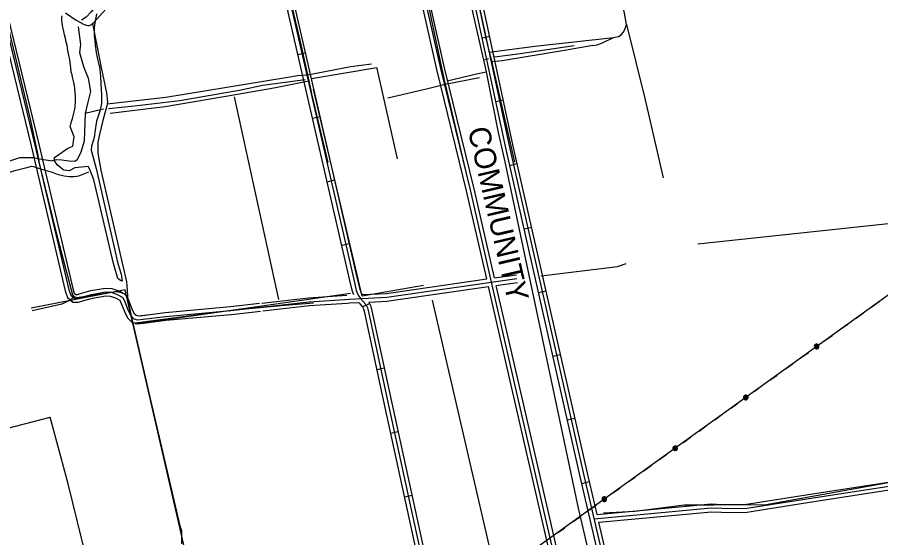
# Model space of a CAD drawing. Extents: x 3424494 to 3462436, y 522220 to 547718.
# Drawn here: x 3456047 to 3459355, y 534289 to 536285 of the extents above; entities that cross this region are included whole.
import ezdxf

# ---------------------------------------------------------------- set-up
doc = ezdxf.new("R2010")
doc.units = 0
for name, color, linetype in [('V-DTCH-CNTR', 7, 'Continuous'), ('V-RIVR-IDEN', 7, 'Continuous'), ('V-ROAD-CNTR', 7, 'Continuous'), ('V-SITE-VEGE', 7, 'Continuous'), ('V-TOPO-SHOR', 7, 'Continuous'), ('V-UTIL-LINE', 7, 'Continuous')]:
    doc.layers.add(name, color=color, linetype=linetype)

msp = doc.modelspace()

# ---------------------------------------------------------------- linework, layer by layer
at = {"layer": 'V-DTCH-CNTR'}
for points in [[(3456711.5, 540227.9), (3456791.8, 539883.8), (3456931.2, 539302.5), (3457055.3, 538754), (3457152.5, 538348.2), (3457303.4, 537680.5), (3457454.1, 537049.8), (3457610.6, 536382.1), (3457681.2, 536050.2), (3457686.5, 536027.5), (3457762.9, 535702)], [(3456761.3, 537785.8), (3456807.2, 537593.5), (3456918.5, 537101.2), (3456990.2, 536787.4), (3456997.1, 536757.5), (3457129.5, 536196.9)], [(3457694.3, 536907.7), (3457839.9, 536215.2), (3457855.4, 536151.1), (3457864.6, 536113), (3457869.4, 536093.2), (3457951.2, 535728.4)], [(3458335.6, 536207.6), (3458350.7, 536210.4), (3458360.2, 536217.3), (3458368.4, 536225.6), (3458373.8, 536238), (3458380.6, 536257.3), (3458373.5, 536299.8), (3458305.7, 536609.7), (3458305.7, 536613.8), (3458308.4, 536617.9), (3458437.3, 536642.1), (3458507.3, 536650.7), (3458588.2, 536662.2), (3458628, 536672), (3458759.6, 536703), (3458780.2, 536707.3), (3458905, 536723.1), (3459238.4, 536770.4), (3459485.3, 536802.1), (3459562.6, 536812.9)], [(3455947.2, 536511.2), (3455964.6, 536439.9), (3456097.1, 535894), (3456124.7, 535762.5), (3456131.3, 535725.6), (3456136.6, 535703.6), (3456196.8, 535458), (3456259.1, 535220.3), (3456264.8, 535212.2), (3456268.2, 535212.2), (3456275.1, 535209.8), (3456426.1, 535232.6), (3456439.9, 535230.2), (3456445.6, 535229), (3456454.8, 535225.4), (3456460.5, 535220.8), (3456462.8, 535218.5), (3456470.7, 535198.8), (3456490.4, 535112.3), (3456554.8, 534828.6), (3456670.1, 534334.8), (3456675.7, 534316.4), (3456676.7, 534295.7), (3456676.4, 534265.7)], [(3456231.6, 536301.3), (3456272.8, 536273.3), (3456303.7, 536256.9), (3456317.5, 536253.3), (3456320.9, 536253.3), (3456324.4, 536253.2), (3456331.3, 536256.6), (3456335.6, 536260.4), (3456341.8, 536265.7), (3456429, 536363.9)], [(3456335.6, 536260.4), (3456368.1, 536091.3), (3456389, 535994.5), (3456392.8, 535959.1), (3456391.4, 535952.6), (3456390, 535945.5), (3456374.5, 535888.5), (3456361.7, 535835.5), (3456356, 535805.6), (3456355.8, 535785.2), (3456355.7, 535763.4), (3456367.3, 535698), (3456451.1, 535331.1), (3456465.5, 535269.7), (3456466.8, 535254.8), (3456470.7, 535198.8)], [(3458380.6, 536257.3), (3458452.4, 535968), (3458521.4, 535669.1)], [(3457855.4, 536151.1), (3458029.6, 536174.2), (3458331, 536207.1), (3458335.6, 536207.6)], [(3458251.5, 536176.1), (3458267.9, 536178.9), (3458288.5, 536185.9), (3458331, 536207.1)], [(3457129.5, 536196.9), (3457158.6, 536064.4), (3457163.7, 536041.2), (3457174.6, 535991.3), (3457236.6, 535728)], [(3458251.5, 536176.1), (3458143.7, 536157.4), (3457905.1, 536117.6), (3457864.6, 536113)], [(3457083.8, 536055.2), (3457120.8, 536060.9), (3457158.6, 536064.4), (3457324.5, 536095.6), (3457404.1, 536105.7)], [(3456391.4, 535952.6), (3456616.2, 535977.8), (3457083.8, 536055.2)], [(3456402.9, 535917), (3456614.2, 535943), (3456891.3, 535990), (3457029.8, 536014.2), (3457163.7, 536041.2)], [(3457466.1, 535976.2), (3457619.6, 536011.4), (3457686.5, 536027.5), (3457818.2, 536053)], [(3455890.7, 535533.4), (3456008.4, 535559.9), (3456005.1, 535578.4), (3455989.9, 535677.5), (3455991, 535679.8), (3455992.2, 535683.2), (3456043, 535697.7), (3456089.2, 535710), (3456101.9, 535713.3), (3456109.9, 535712.1), (3456136.6, 535703.6), (3456180.3, 535690.6), (3456199.8, 535683.5), (3456227.3, 535676.3), (3456245.7, 535673.8), (3456264.1, 535673.7), (3456275.7, 535675.9), (3456282.6, 535677), (3456321.9, 535691.6)], [(3456268.2, 535212.2), (3456245.1, 535197.4), (3456235.8, 535192.9), (3456217.3, 535185), (3456104.3, 535158.4)], [(3456490.4, 535112.3), (3456866.5, 535162), (3457058.5, 535179.3), (3457182.5, 535189.1)], [(3455732.6, 534638.6), (3455788.5, 534651.7), (3455905.8, 534682), (3456173.2, 534751.7)], [(3456368.4, 533980.3), (3456242.4, 534495.9), (3456173.2, 534751.7)]]:
    msp.add_lwpolyline(points, dxfattribs=at)
at = {"layer": 'V-ROAD-CNTR'}
for p, q in [((3457827.5, 536205.6), (3457856.8, 536211.9)), ((3457122.5, 536141.4), (3457151.7, 536148.1)), ((3457879.9, 535961.1), (3457909.2, 535967.4)), ((3457178.5, 535897.7), (3457207.7, 535904.5)), ((3457933.1, 535716.7), (3457962.4, 535723.3)), ((3457234.5, 535654.1), (3457263.7, 535660.8)), ((3457988.3, 535472.9), (3458017.6, 535479.5)), ((3457290.5, 535410.4), (3457319.7, 535417.2)), ((3458043.5, 535229), (3458072.8, 535235.7)), ((3457369.8, 535174.3), (3457396.9, 535187)), ((3458098.8, 534985.2), (3458128, 534991.8)), ((3457424.5, 534934.1), (3457453.8, 534940.4)), ((3458154, 534741.4), (3458183.2, 534748)), ((3457477.2, 534689.7), (3457506.5, 534696.1)), ((3458209.4, 534497.5), (3458238.6, 534504.3)), ((3457530.3, 534445.4), (3457559.6, 534451.8))]:
    msp.add_line(p, q, dxfattribs=at)
for points in [[(3455205.2, 539547.1), (3455574.6, 538012.3), (3455861.5, 536771.8), (3456100.5, 535791.1), (3456230.8, 535235.5), (3456240.2, 535209.6), (3456260.4, 535192.5), (3456269.6, 535192.1)], [(3455234.4, 539554.1), (3455603.8, 538019.2), (3455890.7, 536778.8), (3456129.7, 535798.1), (3456259.6, 535244.1), (3456265.7, 535227.3), (3456272, 535222), (3456277.7, 535221.8), (3456293.7, 535227), (3456328.4, 535236.4), (3456384.6, 535246.5), (3456409.5, 535245), (3456436.1, 535235.8), (3456462.9, 535221.1), (3456472.7, 535199.3), (3456486, 535166.5), (3456494.2, 535149.6), (3456502, 535142), (3456509.2, 535139.7), (3456520.7, 535141)], [(3457845.7, 535281.1), (3457768.1, 535619.6), (3457654.7, 536084.1), (3457424.3, 537108.7), (3457105, 538484.3)], [(3457904.4, 532804), (3458333.9, 532953.1), (3458352.1, 532961.5), (3458363.3, 532968.4), (3458372.4, 532976.8), (3458379.6, 532986.3), (3458384.6, 532993.3), (3458381.1, 533017.4), (3458365.7, 533088.2), (3458203.9, 533788.7), (3458064.2, 534393.6), (3457920.5, 535022), (3457782.7, 535623.1), (3457669.3, 536087.5), (3457438.9, 537112), (3457119.7, 538487.7)], [(3457875.5, 535285.4), (3457797.3, 535626.5), (3457684, 536090.9), (3457453.6, 537115.4), (3457134.3, 538491.1)], [(3457336.2, 535220), (3457331.3, 535232.6), (3457321.5, 535275.4), (3457095.3, 536259.6), (3456835.7, 537394.7), (3456660.7, 538154)], [(3456675.3, 538157.4), (3456850.3, 537398), (3457109.9, 536262.9), (3457336.2, 535278.8), (3457345.7, 535237), (3457352.7, 535219), (3457361.5, 535206.2), (3457372.4, 535195.2), (3457382.3, 535183), (3457388.2, 535170.3), (3457392.6, 535154.9), (3457464.1, 534820.3), (3457607.2, 534162.5), (3457709.5, 533697.4), (3457808.4, 533253.8), (3458020.8, 532281.5), (3458061.7, 532076.5), (3458111.7, 531839.8), (3458138.7, 531712.3)], [(3457369.1, 535221.6), (3457366.1, 535226), (3457360.1, 535241.4), (3457350.8, 535282.1), (3457124.6, 536266.3), (3456864.9, 537401.4), (3456690, 538160.8)], [(3457542.8, 537607.4), (3457689.1, 536922.3), (3457932.7, 535786.6), (3458217.8, 534527.5), (3458420.3, 533657.6), (3458593.6, 532915.5), (3458790.6, 532085.6), (3458862.3, 531774.7)], [(3458405.7, 533654.2), (3458203.2, 534524.2), (3457918, 535783.4), (3457674.4, 536919.1)], [(3458268, 534378), (3458232.4, 534530.9), (3457947.3, 535789.8), (3457703.8, 536925.4)], [(3455876.1, 536775.3), (3456115.1, 535794.6), (3456245.2, 535239.8), (3456253, 535218.5), (3456266.2, 535207.2), (3456279.8, 535206.7), (3456298, 535212.7), (3456331.7, 535221.7), (3456385.5, 535231.4), (3456406.6, 535230.2), (3456430, 535222), (3456451.2, 535210.3), (3456458.9, 535193.4), (3456472.3, 535160.4), (3456481.8, 535140.8), (3456494, 535128.8), (3456507.7, 535124.4), (3456529, 535126.8), (3456615.2, 535137.8), (3456865, 535160.3), (3457164.7, 535194), (3457320, 535204.3), (3457462.8, 535210.9), (3457961.3, 535282.6)], [(3457369.1, 535221.6), (3457461.3, 535225.8), (3457845.7, 535281.1)], [(3457875.5, 535285.4), (3457959.2, 535297.4)], [(3457497.1, 535200.6), (3457852.5, 535251.8)], [(3457917.6, 532824.4), (3458328.3, 532967), (3458345, 532974.8), (3458354.2, 532980.4), (3458361.2, 532986.9), (3458367.5, 532995.2), (3458368.9, 532997.1), (3458366.3, 533014.7), (3458351.1, 533085), (3458189.3, 533785.3), (3458049.6, 534390.2), (3457905.9, 535018.7), (3457852.5, 535251.8)], [(3457882.2, 535256.1), (3457963.4, 535267.7)], [(3458395.7, 532983), (3458400.3, 532989.5), (3458395.9, 533020.1), (3458380.4, 533091.5), (3458218.5, 533792.1), (3458078.9, 534397), (3457935.2, 535025.4), (3457882.2, 535256.1)], [(3456269.6, 535192.1), (3456281.9, 535191.6), (3456302.3, 535198.3), (3456334.9, 535207.1), (3456386.4, 535216.3), (3456403.6, 535215.3), (3456423.9, 535208.3), (3456439.6, 535199.6), (3456445.1, 535187.5), (3456458.6, 535154.3), (3456469.4, 535131.9), (3456486.1, 535115.6), (3456494.6, 535112.8)], [(3456984.3, 535188.8), (3457163.3, 535208.9), (3457309.4, 535218.6)], [(3456515.2, 535140.3), (3456527.2, 535141.7), (3456613.5, 535152.7), (3456863.5, 535175.2), (3456864.2, 535175.3)], [(3456864.2, 535175.3), (3456975.3, 535187.8)], [(3456987.6, 535159), (3457166, 535179), (3457311.4, 535188.7)], [(3457311.4, 535188.7), (3457320.9, 535189.3), (3457355.5, 535190.9)], [(3458124, 531709.2), (3458097, 531836.6), (3458047.1, 532073.5), (3458006.1, 532278.4), (3457793.8, 533250.6), (3457694.9, 533694.1), (3457592.5, 534159.3), (3457449.5, 534817.2), (3457378.1, 535151.2), (3457374.1, 535165), (3457369.4, 535175), (3457361.2, 535185.2), (3457355.5, 535190.9)], [(3457393.7, 535192.7), (3457464.2, 535195.9), (3457497.1, 535200.6)], [(3457917.6, 532824.4), (3457823.1, 533257.1), (3457724.2, 533700.6), (3457621.8, 534165.7), (3457478.8, 534823.5), (3457407.2, 535158.5), (3457402.3, 535175.5), (3457395.1, 535191), (3457393.7, 535192.7)], [(3456518.7, 535110.5), (3456530.8, 535111.9), (3456616.8, 535122.8), (3456866.5, 535145.4), (3456867.5, 535145.5)], [(3456520.7, 535141), (3456527.2, 535141.7), (3456550.6, 535144.7)], [(3456867.5, 535145.5), (3456978.6, 535158)], [(3456494.6, 535112.8), (3456506.2, 535109.1), (3456518.7, 535110.5)], [(3458256.4, 534361.8), (3458705.7, 534403.4), (3458745.7, 534401.9), (3458833.5, 534401.1), (3459071.9, 534438.5), (3459377.4, 534485.7), (3459756.2, 534548.5), (3459927.3, 534575.6), (3460055.3, 534584)], [(3458268, 534378), (3458705.3, 534418.4), (3458746, 534416.9), (3458832.4, 534416.1), (3459069.6, 534453.3), (3459375.1, 534500.5), (3459753.8, 534563.4), (3459925.6, 534590.5), (3460036.9, 534597.8)], [(3458274.9, 534348.5), (3458706.1, 534388.4), (3458745.3, 534386.9), (3458834.6, 534386.1), (3459074.2, 534423.7), (3459379.8, 534470.9), (3459758.6, 534533.7), (3459928.9, 534560.6), (3460043.4, 534568.1)], [(3458512, 533330.6), (3458434.9, 533661), (3458274.9, 534348.5)]]:
    msp.add_lwpolyline(points, dxfattribs=at)
at = {"layer": 'V-SITE-VEGE'}
msp.add_lwpolyline([(3456350.9, 536297.3), (3456347.5, 536281.5), (3456346.6, 536276.7), (3456344.8, 536262.8), (3456342.1, 536244.9), (3456341.6, 536238.2), (3456341.8, 536226), (3456342.2, 536216.4), (3456343.2, 536201.5), (3456343.7, 536196.7), (3456345.3, 536177), (3456349.1, 536149.8), (3456354.8, 536123.6), (3456357.6, 536114), (3456359.8, 536104), (3456361.7, 536095.3), (3456363.6, 536081.7), (3456364.7, 536071.5), (3456366, 536055.6), (3456368.4, 536007.5), (3456369.6, 535986.8), (3456370.2, 535973.5), (3456369.5, 535954.4), (3456367.5, 535942.8), (3456363, 535924), (3456351, 535886), (3456347.7, 535869.7), (3456346.8, 535861.8), (3456345.4, 535852), (3456344.7, 535845.1), (3456343.1, 535832.5), (3456341.2, 535824), (3456337.4, 535810.9), (3456331.6, 535790.5), (3456330.6, 535775), (3456349.9, 535705.3), (3456432.4, 535341), (3456444.6, 535299.7), (3456449.4, 535272.9), (3456442.2, 535275.4), (3456432.4, 535282.7), (3456415.5, 535341), (3456340.2, 535661.6), (3456325.6, 535700.4), (3456318.4, 535712.6), (3456267.4, 535707.7), (3456245.5, 535695.6), (3456226.1, 535698), (3456201.8, 535717.4), (3456189.7, 535734.4), (3456189.7, 535746.6), (3456206.7, 535758.7), (3456240.7, 535783), (3456260.1, 535790.3), (3456264.9, 535826.7), (3456249.2, 535865.9), (3456252.5, 535876.5), (3456256, 535888.6), (3456258.2, 535896.5), (3456264.3, 535917.1), (3456267.5, 535932.4), (3456269.1, 535942.9), (3456270.2, 535960.2), (3456270.4, 535972), (3456270.2, 535982.9), (3456269.4, 535994.5), (3456268.1, 536011.2), (3456266.2, 536021), (3456263.3, 536034), (3456258.9, 536055), (3456257, 536063.2), (3456254.2, 536073.4), (3456253.9, 536078.2), (3456248, 536122.7), (3456246.2, 536132.6), (3456241.1, 536157.2), (3456237.8, 536177), (3456235, 536189.2), (3456232.8, 536198.2), (3456227.9, 536216.6), (3456223.9, 536236), (3456221.5, 536246.2), (3456220.2, 536252.7), (3456218.6, 536263.9), (3456217.9, 536272.1), (3456218.1, 536283.6), (3456219, 536290.2)], dxfattribs=at)
at = {"layer": 'V-TOPO-SHOR'}
for p, q in [((3457852.5, 536124.8), (3457833.6, 536119.9)), ((3457149.9, 536044.5), (3456986.6, 536022.9)), ((3457048.9, 535202.5), (3456879.6, 535979)), ((3456377, 535931.9), (3456307.6, 535915.7)), ((3458654, 535415.5), (3459710.8, 535528.8)), ((3456500.6, 535108.6), (3457323.1, 535226.6))]:
    msp.add_line(p, q, dxfattribs=at)
for points in [[(3457406, 537729), (3457491.6, 537645.8), (3457508.3, 537619.8), (3457513.8, 537606.1), (3457520.8, 537582.8), (3457579.1, 537261.9), (3457675, 536834.1), (3457780.9, 536351.4), (3457833.6, 536119.9), (3457838.7, 536097.8), (3457843.2, 536075.3), (3457889.6, 535842.7), (3457915, 535730.3)], [(3456410.5, 536968.1), (3456449, 536916.6), (3456472, 536857.3), (3456493.9, 536816.5), (3456554.9, 536582.9), (3456556, 536546.1), (3456550.5, 536519.7), (3456549.1, 536497.3), (3456524.6, 536475.4), (3456512.5, 536463.3), (3456484.9, 536453.5), (3456465.3, 536446), (3456432.5, 536431.6), (3456418.2, 536421.9), (3456404.4, 536409.8), (3456389.4, 536385.6), (3456368.1, 536354), (3456330.7, 536305.1), (3456311.2, 536285.5), (3456292.7, 536274)], [(3455786.1, 536402.8), (3455954.9, 535723.4), (3455966.3, 535717.7), (3456057.6, 535746.7), (3456109.1, 535746.9), (3456132, 535741.3), (3456181.1, 535734.3)], [(3456280.1, 536247.8), (3456289.3, 536180.2), (3456285.8, 536149.7), (3456300.8, 536096.2), (3456318.6, 536051.3), (3456328.3, 535999.7), (3456315.6, 535954.2), (3456307.6, 535915.7), (3456305.3, 535845.5), (3456303.5, 535809.3), (3456290.9, 535766.7), (3456277.1, 535737.9), (3456267.3, 535731), (3456244.3, 535732.2), (3456217.8, 535736.2), (3456197.7, 535737.3), (3456181.1, 535734.3)], [(3458180.3, 536174.8), (3457965, 536143.3), (3457875.8, 536131.8)], [(3457503.2, 535741.8), (3457425.6, 536088.7), (3457424.2, 536090.1), (3457174.6, 536048.8)], [(3457693.6, 536040.9), (3457806, 536067.7), (3457843.2, 536075.3)], [(3456986.6, 536022.9), (3456898.9, 536003.7), (3456838.8, 535993.9), (3456669.6, 535964.4), (3456496.4, 535943.9), (3456397, 535933.1)], [(3457603, 535256.4), (3457368.9, 535215.4), (3457182.4, 536009)], [(3457915, 535730.3), (3458196, 534402.7), (3458830.1, 531684.6), (3459491.5, 528866.9), (3459752.7, 527750.7)], [(3458054.4, 535292.8), (3458345.7, 535328.4), (3458380, 535339.9)], [(3457282, 531671.4), (3456798.1, 533772.5), (3456460, 535239.8), (3456100.3, 535169.6)], [(3457917, 532817.3), (3458168, 532909.9), (3457993.2, 533663.6), (3457637.6, 535199.4)], [(3458292.8, 534385.1), (3458412.8, 534391.3), (3458601.3, 534415), (3458715.6, 534415.5), (3458915.7, 534416.5), (3459503.9, 534522), (3460023.6, 534610.1)]]:
    msp.add_lwpolyline(points, dxfattribs=at)
at = {"layer": 'V-UTIL-LINE'}
for points in [[(3460250.6, 535842.7), (3459015, 534954.5), (3457624.1, 533953.2), (3456242.4, 532954.9), (3454854.4, 531959.1), (3452977, 530612.1), (3449895.7, 529750.1), (3448530.5, 529366.4)], [(3459321, 535174.5), (3459348.6, 535194.3)], [(3459260.9, 535131.3), (3459288.5, 535151.1)], [(3459200.9, 535088.1), (3459228.5, 535107.9)], [(3459140.8, 535044.9), (3459168.4, 535064.7)], [(3459109.1, 535022.1), (3459106.4, 535023.1), (3459107, 535020.8), (3459109.6, 535020), (3459111.8, 535022), (3459110, 535024.8), (3459105.4, 535025.7), (3459103.2, 535022), (3459104.9, 535017.4), (3459109.4, 535016.4), (3459113.5, 535018.2), (3459114.7, 535022.9), (3459111.8, 535027.5), (3459103.9, 535029.4), (3459101.5, 535026.9), (3459100.2, 535023.6), (3459100.4, 535020.1), (3459101.8, 535016.9), (3459104.4, 535014.5), (3459107.7, 535013.2), (3459111.2, 535013.4), (3459114.4, 535014.8), (3459116.8, 535017.4), (3459118, 535020.7), (3459117.9, 535024.2), (3459116.4, 535027.4), (3459113.9, 535029.8), (3459110.6, 535031), (3459107.1, 535030.9), (3459103.9, 535029.4)], [(3459049.8, 534979.5), (3459077.4, 534999.3)], [(3458989.8, 534936.3), (3459015, 534954.5), (3459017.4, 534956.2)], [(3458929.7, 534893.1), (3458957.3, 534912.9)], [(3458869.6, 534849.8), (3458897.2, 534869.7)], [(3458838, 534827.1), (3458835.3, 534828), (3458835.9, 534825.8), (3458838.5, 534824.9), (3458840.7, 534826.9), (3458838.9, 534829.7), (3458834.2, 534830.6), (3458832.1, 534826.9), (3458833.8, 534822.3), (3458838.3, 534821.4), (3458842.4, 534823.1), (3458843.6, 534827.8), (3458840.7, 534832.4), (3458832.8, 534834.4), (3458830.4, 534831.8), (3458829.1, 534828.5), (3458829.3, 534825), (3458830.7, 534821.8), (3458833.3, 534819.4), (3458836.6, 534818.2), (3458840.1, 534818.3), (3458843.3, 534819.8), (3458845.7, 534822.3), (3458846.9, 534825.6), (3458846.8, 534829.1), (3458845.3, 534832.3), (3458842.8, 534834.7), (3458839.5, 534835.9), (3458836, 534835.8), (3458832.8, 534834.4)], [(3458778.7, 534784.4), (3458806.3, 534804.3)], [(3458718.7, 534741.2), (3458746.3, 534761)], [(3458658.6, 534697.9), (3458686.2, 534717.8)], [(3458598.6, 534654.7), (3458626.2, 534674.6)], [(3458566.9, 534631.9), (3458564.2, 534632.9), (3458564.9, 534630.6), (3458567.5, 534629.8), (3458569.6, 534631.8), (3458567.8, 534634.6), (3458563.2, 534635.5), (3458561.1, 534631.8), (3458562.8, 534627.2), (3458567.2, 534626.2), (3458571.3, 534628), (3458572.6, 534632.7), (3458569.6, 534637.3), (3458561.7, 534639.2), (3458559.3, 534636.7), (3458558.1, 534633.4), (3458558.2, 534629.9), (3458559.6, 534626.7), (3458562.2, 534624.3), (3458565.5, 534623), (3458569, 534623.2), (3458572.2, 534624.6), (3458574.6, 534627.2), (3458575.8, 534630.5), (3458575.7, 534634), (3458574.2, 534637.2), (3458571.7, 534639.6), (3458568.4, 534640.8), (3458564.9, 534640.7), (3458561.7, 534639.2)], [(3458507.7, 534589.3), (3458535.3, 534609.1)], [(3458447.6, 534546), (3458475.2, 534565.9)], [(3458387.6, 534502.8), (3458415.2, 534522.7)], [(3458327.5, 534459.6), (3458355.1, 534479.4)], [(3458295.9, 534436.8), (3458293.2, 534437.8), (3458293.8, 534435.5), (3458296.4, 534434.7), (3458298.6, 534436.6), (3458296.7, 534439.5), (3458292.1, 534440.3), (3458290, 534436.6), (3458291.7, 534432.1), (3458296.2, 534431.1), (3458300.3, 534432.9), (3458301.5, 534437.5), (3458298.5, 534442.2), (3458290.6, 534444.1), (3458288.2, 534441.5), (3458287, 534438.2), (3458287.1, 534434.7), (3458288.6, 534431.5), (3458291.1, 534429.1), (3458294.4, 534427.9), (3458297.9, 534428), (3458301.1, 534429.5), (3458303.5, 534432.1), (3458304.8, 534435.3), (3458304.6, 534438.9), (3458303.2, 534442.1), (3458300.6, 534444.4), (3458297.3, 534445.7), (3458293.8, 534445.6), (3458290.6, 534444.1)], [(3458236.6, 534394.1), (3458264.2, 534414)], [(3458176.5, 534350.9), (3458204.1, 534370.8)], [(3458116.5, 534307.7), (3458144.1, 534327.5)]]:
    msp.add_lwpolyline(points, dxfattribs=at)

# ---------------------------------------------------------------- texts
at = {"layer": 'V-RIVR-IDEN'}
msp.add_text('COMMUNITY', height=83, rotation=283.1164, dxfattribs=at).set_placement((3457771.9, 535854.6))

doc.saveas('drawing.dxf')
